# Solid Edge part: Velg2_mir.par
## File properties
Author: KULL
Template: Iso Metric Part.par
Last saved by: KULL
Revision: 2
Application: Solid Edge
Accuracy: 0,990
Username: KULL
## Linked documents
Velg2.par
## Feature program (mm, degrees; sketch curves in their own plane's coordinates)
part copy "CopiedPart_1"
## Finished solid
Body 1: solid body, 389 faces, 931 edges, 512 vertices.
  Faces by surface: blend 256, torus 63, swept 32, cylinder 24, cone 10, plane 2, spun 2
  Edges by curve: intersection 512, circle 403, line 16
Bounding box of the edges (mm; curved faces can reach further): 43.118 x 87.299 x 87.299, from (-41.1766, -43.6493, -43.6493) to (1.9413, 43.6493, 43.6493).
Cylindrical faces by radius (mm): R4 x1, R8 x1, R10 x1, R36.3826 x1, R38.3116 x17, R38.3826 x1, R40.3116 x2
Conical faces (half-angle, radius in mm at the cone's reference point): 14.1898 deg R43.1591 x1, 14.1898 deg R43.6493 x1, 17.3646 deg R36.5649 x1, 17.3646 deg R38.1293 x1, 17.3646 deg R38.5649 x1, 17.3646 deg R40.1293 x1, 75.8102 deg R41.0291 x1, 75.8102 deg R41.5194 x1, 75.8102 deg R43.1591 x1, 75.8102 deg R43.6493 x1
Toroidal faces (ring radius, tube radius in mm): R8.1 r0.1 x1, R13 r3 x1, R34.3116 r4 x17, R36.3116 r4 x2, R36.7771 r0.6 x16, R38.0022 r0.6 x16, R40.3826 r4 x2, R41.9116 r1.6 x2, R41.9116 r3.6 x2, R42.3826 r4 x2, R43.0142 r0.2 x2
Planar faces by outward normal: +x 1, -x 1
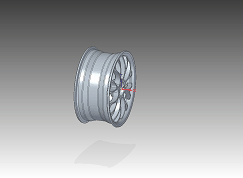
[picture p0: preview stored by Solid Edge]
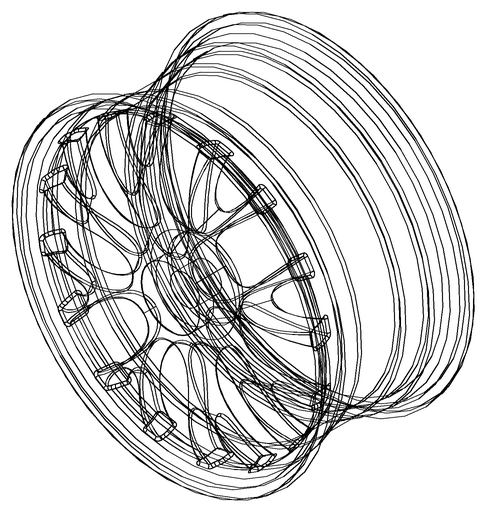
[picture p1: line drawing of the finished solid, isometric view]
